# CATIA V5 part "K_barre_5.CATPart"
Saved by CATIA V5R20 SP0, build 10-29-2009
Part number: barre_5
Bounding box of the stored display mesh (mm): x -50.981 to -11.018, y -2 to -1, z -10.505 to -4.008
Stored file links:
  G:\Khaled_CFAO_2011\ST2M\ST2M_GR2\gcausse\Khaled\CAD_ThinkMotion\K_barre_5.CATPart
  C:\Documents and Settings\gcausse\Bureau\video thinkmotio\assemblage_gcausse\pupitre_think.CATProduct
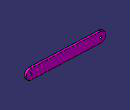
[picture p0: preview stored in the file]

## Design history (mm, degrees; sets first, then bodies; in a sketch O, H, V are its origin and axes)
Set1
  Sketch1 on Plane1, origin (0, -1, 0), H (-1, 0, 0), V (0, 0, 1)
    line L1 (48.3762, -10.5055) -> (13.4084, -9.0036)
    arc A1 centre (13.5157, -6.5059) radius 2.5 from (13.4084, -9.0036) to (13.6229, -4.0082) cw
    point P3 (13.5157, -6.5059)
    line L2 (13.6229, -4.0082) -> (48.5907, -5.5101)
    arc A2 centre (48.4834, -8.0078) radius 2.5 from (48.5907, -5.5101) to (48.3762, -10.5055) cw
    point P6 (48.4834, -8.0078)
    reference projected point E1 (13.5157, -6.5059) from Point1
    reference projected line E2 (48.4834, -8.0078) -> (13.5157, -6.5059) from Line1
    reference projected point E3 (48.4834, -8.0078) from Point2
    distance L2 L1 = 5
    tangency: A1 L1, L2 A1, A2 L2, L1 A2
    coincidence: P3 E1, P6 E3
    parallelism: L2 E2
Set2
  Plane1: linked copy from another document
  Point1: linked copy from another document
  Line1: linked copy from another document
  Point2: linked copy from another document
Body1 (main body)
  Pad1: profile Sketch1, direction (0, -1, 0), length 1
  Sketch2 on start face of Pad1, origin (-39.2275, -1, -8.0052), H (1, 0, 0), V (0, 0, -1)
    point P1 (-9.2559, 0.0026)
    reference projected point E1 (-9.2559, 0.0026) from Point2
    coincidence: P1 E1
  Hole1: placed by Sketch2, at (-48.4834, -1, -8.0078) direction (0, -1, 0), diameter 1, depth 1
  Sketch3 on start face of Pad1, origin (-18.8254, -1, -6.368), H (1, 0, 0), V (0, 0, -1)
    point P1 (5.3097, 0.1379)
    reference projected point E1 (5.3097, 0.1379) from Point1
    coincidence: P1 E1
  Hole2: placed by Sketch3, at (-13.5157, -1, -6.5059) direction (0, -1, 0), diameter 1, depth 1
